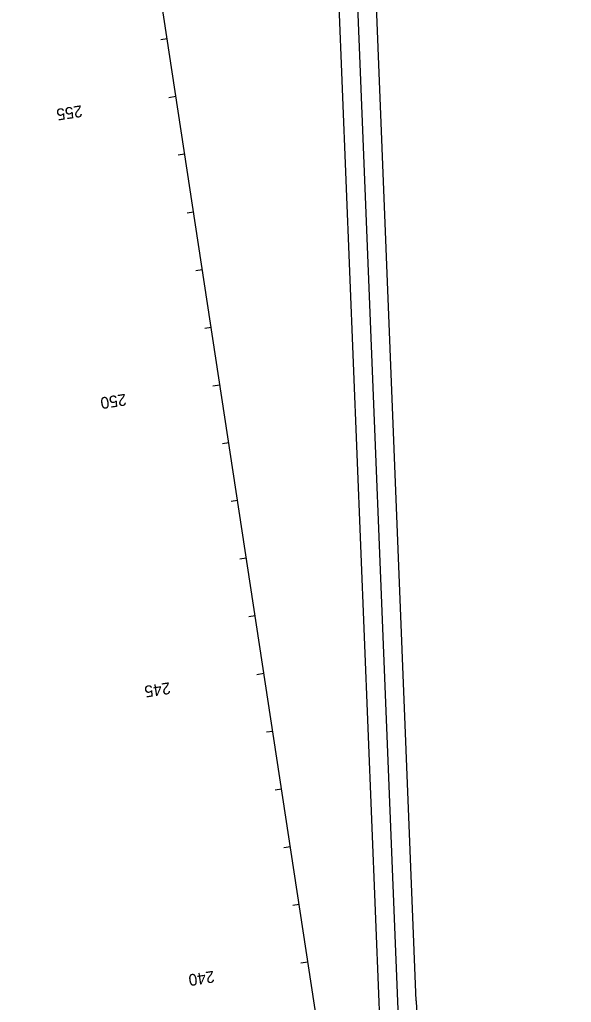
# Model space of a CAD drawing. Extents: x 5180909 to 5237144, y 3695282 to 3720102.
# Drawn here: x 5196966 to 5197911, y 3707425 to 3709109 of the extents above; entities that cross this region are included whole.
import ezdxf

# ---------------------------------------------------------------- set-up
doc = ezdxf.new("R2010")
doc.units = 0
for name, color, linetype in [('Alignment', 7, 'Continuous'), ('Default', 7, 'Continuous'), ('DisFieldPoint', 7, 'Continuous'), ('dsnEntrancePaved', 7, 'Continuous'), ('dsnShadingGranular', 7, 'Continuous'), ('dsnSidewalkShadingRamp', 7, 'Continuous')]:
    doc.layers.add(name, color=color, linetype=linetype)

msp = doc.modelspace()

# ---------------------------------------------------------------- linework, layer by layer
at = {"layer": 'Alignment'}
msp.add_line((5197884.8, 3704711.8), (5196965.6, 3710730.6), dxfattribs=at)
at = {"layer": 'Default'}
msp.add_line((5197884.8, 3704711.8), (5196965.6, 3710730.6), dxfattribs=at)
at = {"layer": 'DisFieldPoint'}
for p, q in [((5197581.7, 3707425.2), (5197504.8, 3709343.4)), ((5197613.7, 3707426.4), (5197536.8, 3709344.6)), ((5197645.6, 3707427.7), (5197568.8, 3709345.9))]:
    msp.add_line(p, q, dxfattribs=at)
for radius in [11491.2, 11459.2, 11427.2]:
    msp.add_arc((5209063.6, 3707885.2), radius, 182.29445, 186.37961, dxfattribs=at)
at = {"layer": 'dsnEntrancePaved'}
msp.add_line((5197884.8, 3704711.8), (5196965.6, 3710730.6), dxfattribs=at)
at = {"layer": 'dsnShadingGranular'}
for p in [(5197884.8, 3704711.8), (5197911.5, 3704537)]:
    msp.add_line(p, (5196965.6, 3710730.6), dxfattribs=at)
at = {"layer": 'dsnSidewalkShadingRamp'}
for p, q in [((5197218.3, 3709075.7), (5197207.4, 3709074)), ((5197233.4, 3708976.8), (5197221.3, 3708975)), ((5197248.5, 3708878), (5197237.6, 3708876.3)), ((5197263.6, 3708779.1), (5197252.7, 3708777.4)), ((5197278.7, 3708680.2), (5197267.8, 3708678.6)), ((5197293.8, 3708581.4), (5197282.9, 3708579.7)), ((5197308.9, 3708482.5), (5197296.8, 3708480.7)), ((5197324, 3708383.7), (5197313.1, 3708382)), ((5197339.1, 3708284.8), (5197328.2, 3708283.2)), ((5197354.2, 3708186), (5197343.3, 3708184.3)), ((5197369.3, 3708087.1), (5197358.4, 3708085.5)), ((5197384.4, 3707988.3), (5197372.3, 3707986.4)), ((5197399.5, 3707889.4), (5197388.6, 3707887.8)), ((5197414.6, 3707790.6), (5197403.7, 3707788.9)), ((5197429.7, 3707691.7), (5197418.8, 3707690)), ((5197444.8, 3707592.9), (5197433.9, 3707591.2)), ((5197459.9, 3707494), (5197447.8, 3707492.2))]:
    msp.add_line(p, q, dxfattribs=at)

# ---------------------------------------------------------------- texts
for s, p in [('255', (5197071.5, 3708962.2)), ('250', (5197147, 3708467.9)), ('245', (5197222.5, 3707973.7)), ('240', (5197298, 3707479.4))]:
    msp.add_text(s, height=20, rotation=188.6831, dxfattribs=at).set_placement(p)

doc.saveas('drawing.dxf')
